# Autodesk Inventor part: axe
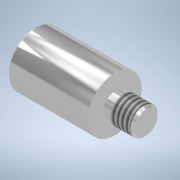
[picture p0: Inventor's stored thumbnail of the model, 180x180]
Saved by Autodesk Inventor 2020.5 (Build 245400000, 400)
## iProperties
Created: 2022-10
Part Number: axe
Material: Aluminium 6061
Document SubType Name: Modeling
Designer: mel
Density: 2.7 g/cm^3
Appearance: Aluminium - Plat
Author: mel
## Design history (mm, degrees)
sketch "Esquisse1"
  geometry: L1 (0, 0)-(25, 0); L2 (25, 0)-(25, 3); L3 (0, 6)-(0, 0); L4 (25, 0)-(20, 0); L5 (20, 0)-(20, 3); L6 (20, 3)-(25, 3); L7 (25, 3)-(25, 0); L8 (20, 2.5)-(18, 2.5); L9 (18, 2.5)-(18, 6); L10 (20, 3)-(20, 2.5); L11 (18, 6)-(0, 6)
  constraints: 22 end point, 5 parallel, 3 horizontal, 3 perpendicular, 1 point on line
  dimensions: "d2" = 5 distance of L5.end L2.end; "d3" = 3 distance of L5.end L4.end; "d4" = 2.5 distance between parallel lines of L1 L8; "d5" = 2 distance between parallel lines of L10 L9; "d12" = 6 distance between parallel lines of L11 L1
revolve "Révolution1" sketch "Esquisse1" stored, may be unused: angle "d6" = 90 deg
feature "Filetage1" dims "d7" = 5, "d8" = 0
chamfer "Chanfrein1" distance "d9" = 0.5; stored, may be unused: second distance "d10" = 2, angle "d11" = 45 deg
node "Solide1"
